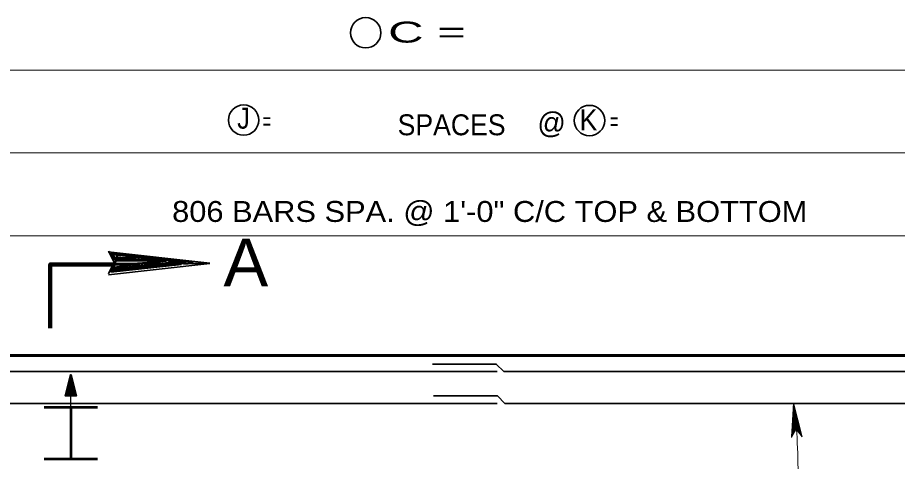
# Model space of a CAD drawing. Extents: x 144 to 252, y 360 to 425.
# Drawn here: x 160.77 to 174.56, y 398.8 to 405.76 of the extents above; entities that cross this region are included whole.
import ezdxf
from ezdxf.enums import TextEntityAlignment as Align

# ---------------------------------------------------------------- set-up
doc = ezdxf.new("R2010")
doc.units = 0
doc.header["$LTSCALE"] = 0.13
for name, color, linetype, lineweight in [('1', 7, 'Continuous', 40), ('10', 7, 'Continuous', 35), ('16', 7, 'Continuous', 13), ('3', 7, 'Continuous', 13), ('9', 7, 'Continuous', 25)]:
    doc.layers.add(name, color=color, linetype=linetype, lineweight=lineweight)

msp = doc.modelspace()

# ---------------------------------------------------------------- linework, layer by layer
at = {"layer": '1', "lineweight": 13}
msp.add_line((177.3103, 402.3377), (157.2677, 402.3377), dxfattribs=at)
at = {"layer": '1', "lineweight": 35}
for p, q in [((162.1939, 402.0859), (163.7839, 401.9089)), ((162.2299, 402.0439), (163.4119, 401.9149)), ((162.2329, 402.0709), (163.4179, 401.9419)), ((162.2329, 402.0649), (163.4179, 401.9389)), ((162.2329, 402.0589), (163.4119, 401.9269)), ((162.2359, 402.0769), (163.4179, 401.9479)), ((163.7869, 401.9059), (162.1969, 401.7289)), ((162.1969, 401.9029), (163.7869, 401.9029)), ((162.2269, 401.8219), (163.3309, 401.9419)), ((162.2299, 401.8039), (163.3309, 401.9239)), ((162.2329, 401.7859), (163.3369, 401.9059)), ((162.2359, 401.7709), (163.3399, 401.8909)), ((156.5478, 400.2095), (168.2861, 400.2095)), ((168.3901, 400.2095), (180.0478, 400.2095)), ((156.5478, 399.7095), (168.2861, 399.7095)), ((168.4074, 399.7095), (180.0478, 399.7095))]:
    msp.add_line(p, q, dxfattribs=at)
at = {"layer": '1', "lineweight": 60}
msp.add_line((156.2978, 400.4595), (180.2978, 400.4595), dxfattribs=at)
msp.add_line((156.2978, 400.4595), (180.2978, 400.4595), dxfattribs=at)
at = {"layer": '1', "lineweight": 25}
msp.add_line((161.6073, 399.6498), (161.6073, 400.1498), dxfattribs=at)
at = {"layer": '1', "lineweight": 53}
for p, q in [((161.1875, 399.6498), (162.0271, 399.6498)), ((161.6073, 399.6498), (161.6073, 398.8415)), ((161.1876, 398.8415), (162.0272, 398.8415))]:
    msp.add_line(p, q, dxfattribs=at)
at = {"layer": '1', "lineweight": 35}
for points in [[(162.1999, 401.7439), (162.2839, 401.9239), (162.1999, 402.0979)], [(162.3079, 401.9419), (163.0159, 401.9509), (163.0129, 401.9329), (162.8749, 401.9419), (162.3079, 401.9509), (162.7639, 401.9659), (162.2869, 401.9749), (162.6229, 401.9869), (162.2749, 402.0049), (162.8179, 401.9629), (163.5259, 401.9329), (163.3789, 401.8939), (163.5739, 401.9119), (162.3079, 401.9059), (162.6769, 401.8819), (162.2869, 401.8819), (163.0969, 401.9389), (162.2809, 401.8489), (162.3109, 401.9389), (162.2449, 402.0499), (162.2809, 402.0259), (162.3109, 401.9629), (162.3529, 401.9809), (162.3259, 402.0319), (162.3019, 401.9179), (162.2689, 401.8489), (162.2359, 401.7709)]]:
    msp.add_lwpolyline(points, dxfattribs=at)
for centre in [(166.2269, 405.5222), (164.3146, 404.1532), (169.7332, 404.1462)]:
    msp.add_circle(centre, 0.238, dxfattribs=at)
at = {"layer": '10'}
for p, q in [((161.6069, 399.8277), (161.6069, 400.1629)), ((161.5592, 399.8277), (161.5664, 400.0002)), ((161.592, 400.0116), (161.5843, 399.8277)), ((161.5983, 400.0115), (161.5906, 399.8277)), ((161.5969, 399.8277), (161.6046, 400.0113)), ((161.6108, 400.0112), (161.6032, 399.8277))]:
    msp.add_line(p, q, dxfattribs=at)
for points in [[(161.6904, 399.8277), (161.5235, 399.8277), (161.6068, 400.1629)], [(161.6904, 399.8277), (161.6068, 400.1629), (161.6904, 399.8277)]]:
    msp.add_lwpolyline(points, dxfattribs=at)
msp.add_lwpolyline([(161.6068, 400.1629), (161.6904, 399.8277), (161.5235, 399.8277), (161.6904, 399.8277)], close=True, dxfattribs=at)
at = {"layer": '16', "lineweight": 106}
msp.add_lwpolyline([(161.2846, 400.8898), (161.2846, 401.8898), (162.2846, 401.8898)], dxfattribs=at)
at = {"layer": '16'}
msp.add_arc((165.653, 398.6917), 7.3474, 358.12487, 8.06122, dxfattribs=at)
at = {"layer": '3'}
for p, q in [((156.2728, 404.9348), (180.2736, 404.9348)), ((156.2738, 403.6397), (178.9784, 403.6397)), ((172.9278, 399.722), (172.8962, 399.1779)), ((172.9287, 399.7076), (172.8982, 399.1814)), ((172.9298, 399.6968), (172.9001, 399.1848)), ((172.9314, 399.6825), (172.9028, 399.1894)), ((172.9327, 399.6698), (172.9051, 399.1934)), ((172.9339, 399.6585), (172.9071, 399.197)), ((172.9355, 399.6442), (172.9098, 399.2016)), ((172.9368, 399.6315), (172.9122, 399.2056)), ((172.9382, 399.6178), (172.9146, 399.2099)), ((172.9719, 399.3089), (172.9278, 399.722)), ((173.0634, 399.1846), (172.9278, 399.722)), ((173.0592, 399.1902), (172.9287, 399.7076)), ((173.0569, 399.1935), (172.9298, 399.6968)), ((173.0538, 399.1977), (172.9314, 399.6825)), ((173.0509, 399.2016), (172.9327, 399.6698)), ((173.0509, 399.2016), (172.9327, 399.6698)), ((173.0484, 399.205), (172.9339, 399.6585)), ((173.0452, 399.2092), (172.9355, 399.6442)), ((173.0424, 399.213), (172.9368, 399.6315)), ((173.0395, 399.2172), (172.9382, 399.6178)), ((172.9398, 399.6041), (172.9172, 399.2143)), ((172.9412, 399.5909), (172.9196, 399.2185)), ((172.9427, 399.5771), (172.9221, 399.2229)), ((172.944, 399.5646), (172.9244, 399.2269)), ((172.9452, 399.5532), (172.9265, 399.2306)), ((172.9468, 399.5377), (172.9293, 399.2355)), ((172.9483, 399.5239), (172.9319, 399.2398)), ((172.9497, 399.5059), (172.9345, 399.2444)), ((172.9512, 399.4921), (172.937, 399.2489)), ((172.9526, 399.479), (172.9394, 399.253)), ((173.0364, 399.2212), (172.9398, 399.6041)), ((173.0335, 399.2252), (172.9412, 399.5909)), ((173.0304, 399.2294), (172.9427, 399.5771)), ((173.0277, 399.2332), (172.944, 399.5646)), ((173.0251, 399.2367), (172.9452, 399.5532)), ((173.0217, 399.2413), (172.9468, 399.5377)), ((173.0186, 399.2454), (172.9483, 399.5239)), ((173.0137, 399.2522), (172.9497, 399.5059)), ((173.0107, 399.2562), (172.9512, 399.4921)), ((173.0159, 399.2492), (172.9515, 399.5045)), ((173.0077, 399.2602), (172.9526, 399.479)), ((172.9541, 399.47), (172.9417, 399.257)), ((172.9553, 399.4581), (172.944, 399.2608)), ((172.9568, 399.4443), (172.9465, 399.2652)), ((172.9585, 399.4287), (172.9493, 399.2702)), ((172.9598, 399.4162), (172.9516, 399.2742)), ((172.9613, 399.4031), (172.954, 399.2783)), ((173.0067, 399.2616), (172.9541, 399.47)), ((173.0041, 399.2652), (172.9553, 399.4581)), ((172.9625, 399.3912), (172.9562, 399.2822)), ((173.001, 399.2693), (172.9568, 399.4443)), ((172.9976, 399.2741), (172.9585, 399.4287)), ((172.964, 399.3767), (172.9588, 399.2867)), ((172.9947, 399.2778), (172.9598, 399.4162)), ((172.9918, 399.2818), (172.9613, 399.4031)), ((172.9655, 399.363), (172.9613, 399.2912)), ((172.9892, 399.2854), (172.9625, 399.3912)), ((172.9668, 399.3503), (172.9637, 399.2952)), ((172.9861, 399.2897), (172.964, 399.3767)), ((172.983, 399.2938), (172.9655, 399.363)), ((172.9802, 399.2977), (172.9668, 399.3503)), ((172.8962, 399.1779), (172.9717, 399.3092)), ((172.9682, 399.3372), (172.9661, 399.2993)), ((172.9695, 399.3258), (172.9682, 399.303)), ((172.9748, 399.3051), (172.9695, 399.3258)), ((172.9705, 399.3157), (172.9701, 399.3062)), ((172.9767, 399.3026), (172.9704, 399.3271)), ((172.9717, 399.3092), (173.0634, 399.1846))]:
    msp.add_line(p, q, dxfattribs=at)
at = {"layer": '3', "lineweight": 35}
for points in [[(168.3901, 400.2095), (168.2722, 400.3273), (167.2722, 400.3273)], [(168.4074, 399.7095), (168.2896, 399.8273), (167.2896, 399.8273)]]:
    msp.add_lwpolyline(points, dxfattribs=at)
at = {"layer": '9'}
for p, q in [((161.5739, 400.0307), (161.5732, 400.0121)), ((161.5815, 400.0611), (161.5795, 400.0119)), ((161.5891, 400.0914), (161.5857, 400.0118)), ((161.5967, 400.1218), (161.592, 400.0116)), ((161.6042, 400.1522), (161.5983, 400.0115)), ((161.6103, 400.1489), (161.6046, 400.0113)), ((161.6157, 400.1273), (161.6108, 400.0112)), ((161.6211, 400.1057), (161.6172, 400.011)), ((161.6265, 400.0841), (161.6234, 400.0108)), ((161.6318, 400.0625), (161.6298, 400.0107)), ((161.6372, 400.0409), (161.636, 400.0105)), ((161.5437, 399.9091), (161.5403, 399.8277)), ((161.5512, 399.9395), (161.5466, 399.8277)), ((161.5588, 399.9699), (161.5528, 399.8277)), ((161.5732, 400.0121), (161.5654, 399.8277)), ((161.5795, 400.0119), (161.5718, 399.8277)), ((161.5857, 400.0118), (161.5781, 399.8277)), ((161.6172, 400.011), (161.6095, 399.8277)), ((161.6234, 400.0108), (161.6157, 399.8277)), ((161.6298, 400.0107), (161.622, 399.8277)), ((161.636, 400.0105), (161.6283, 399.8277)), ((161.6422, 400.0103), (161.6347, 399.8277)), ((161.648, 399.9977), (161.6409, 399.8277)), ((161.6426, 400.0192), (161.6422, 400.0103)), ((161.6534, 399.9761), (161.6472, 399.8277)), ((161.6587, 399.9545), (161.6535, 399.8277)), ((161.6642, 399.9329), (161.6598, 399.8277)), ((161.6696, 399.9113), (161.6661, 399.8277)), ((161.6749, 399.8897), (161.6723, 399.8277)), ((161.5286, 399.8483), (161.5277, 399.8277)), ((161.5362, 399.8787), (161.534, 399.8277)), ((161.6803, 399.8681), (161.6787, 399.8277)), ((161.6857, 399.8465), (161.6849, 399.8277))]:
    msp.add_line(p, q, dxfattribs=at)
at = {"layer": '9', "lineweight": 40}
msp.add_lwpolyline([(161.6068, 400.1629), (161.6904, 399.8277), (161.5235, 399.8277)], close=True, dxfattribs=at)

# ---------------------------------------------------------------- texts
at = {"layer": '1'}
for s, height, width, p in [('J', 0.3281, 0.9, (164.3121, 404.0185)), ('K', 0.3281, 0.95, (169.717, 403.9924)), ('=', 0.2833, 0.6, (164.6801, 403.9958)), ('=', 0.2833, 0.6, (170.1189, 403.9922))]:
    msp.add_text(s, height=height, dxfattribs=dict(at, width=width)).set_placement(p, align=Align.CENTER)
at = {"layer": '1', "width": 0.95}
msp.add_text('SPACES', height=0.3281, dxfattribs=at).set_placement((166.7272, 403.9149))
at = {"layer": '1'}
msp.add_text('@', height=0.3281, dxfattribs=at).set_placement((169.1393, 403.9475), align=Align.CENTER)
at = {"layer": '16', "width": 1.75}
msp.add_text('C =      ', height=0.3281, dxfattribs=at).set_placement((167.8271, 405.3682), align=Align.CENTER)
at = {"layer": '16'}
for s, height, width, p in [('806 BARS SPA. @ 1\'-0" C/C TOP & BOTTOM', 0.3281, 1.1, (163.1942, 402.5561)), ('A', 0.75, 1.05, (163.9979, 401.5452))]:
    msp.add_text(s, height=height, dxfattribs=dict(at, width=width)).set_placement(p)

doc.saveas('drawing.dxf')
